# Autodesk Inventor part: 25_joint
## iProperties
Shininess: 20.0
Length Units: 11270
Angle Units: 11279
Time Units: 11290
Mass Units: 11283
Length Display Precision: 3
Angle Display Precision: 2
Created: 2000-10
Part Number: 25_joint
Material: Par défaut
Document SubType Name: Modélisation
Density: 0.0
Volumn: 0.0
Area: 0.0
PropertySet Name: Model Information
Control State: 0
Master: False
Checked Out: False
Author: Laurent GAUTHERON
